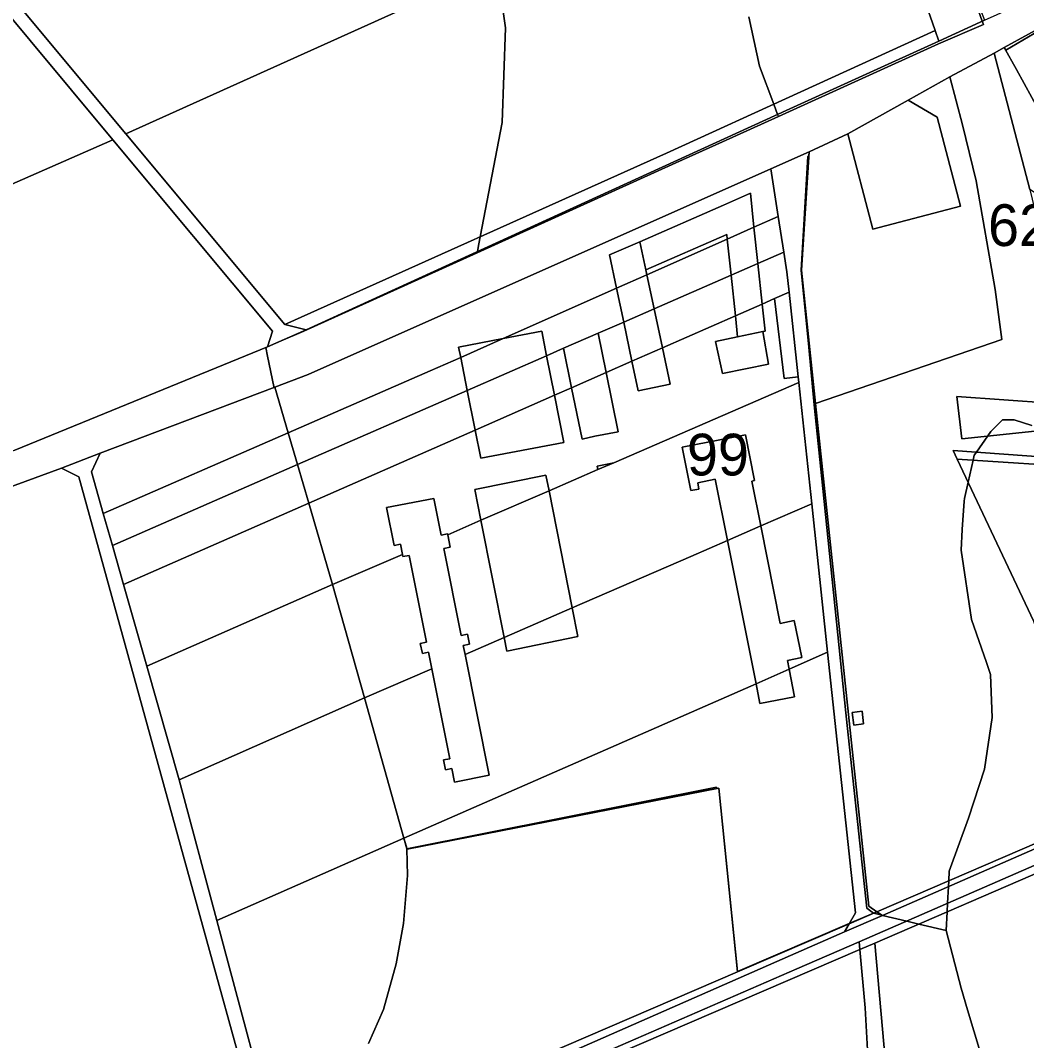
# Model space of a CAD drawing. Extents: x -522079 to -518792, y -1142400 to -1139961.
# Drawn here: x -520985.3 to -520623.1, y -1141173.1 to -1140806 of the extents above; entities that cross this region are included whole.
import ezdxf

# ---------------------------------------------------------------- set-up
doc = ezdxf.new("R2010")
doc.units = 0
for name, color, linetype in [('Bonity', 7, 'Continuous'), ('Hranice parcel', 7, 'Continuous'), ('Parcelní čísla', 7, 'Continuous'), ('Poz předměty', 7, 'Continuous'), ('Značky bodu BP', 7, 'Continuous'), ('Značky budov', 7, 'Continuous'), ('Značky kultur', 7, 'Continuous')]:
    doc.layers.add(name, color=color, linetype=linetype)

msp = doc.modelspace()

# ---------------------------------------------------------------- linework, layer by layer
at = {"layer": 'Bonity'}
for points in [[(-520699.09, -1140943.92), (-520704.17, -1140895.93), (-520701.37, -1140853.35), (-520687.49, -1140846.81), (-520678.48, -1140881.15), (-520646.86, -1140872.86), (-520655.25, -1140840.87), (-520665.74, -1140834.79), (-520650.7, -1140826.31), (-520646.19, -1140843.58), (-520641.23, -1140863.72), (-520634.37, -1140902.81), (-520632.04, -1140920.85)], [(-520879.25, -1141251.61), (-520880.53, -1141246.97), (-520885.33, -1141230.38), (-520883.56, -1141226.59), (-520683.09, -1141140.3), (-520681.18, -1141161.32), (-520680.34, -1141176.38), (-520746.65, -1141201.66), (-520746.38, -1141203.48), (-520757.5, -1141209.45), (-520763.86, -1141219.18), (-520792.12, -1141217.97)]]:
    msp.add_lwpolyline(points, close=True, dxfattribs=at)
at = {"layer": 'Hranice parcel'}
for points in [[(-520657.77, -1140804.5), (-520664.94, -1140785.33), (-520669.15, -1140773.31), (-520674.16, -1140762.17), (-520682.43, -1140743.84), (-520689.02, -1140730.38), (-520701.8, -1140708.2), (-520711.88, -1140691.39), (-520722.11, -1140674.56), (-520715.02, -1140671.04), (-520673.31, -1140722.41), (-520669.12, -1140730.36), (-520666.3, -1140735.71), (-520657.82, -1140755.57), (-520652.69, -1140766.32), (-520641.11, -1140798.37), (-520638.22, -1140805.93), (-520654.73, -1140813.47), (-520656.02, -1140809.72)], [(-520615.7, -1140843.89), (-520626.71, -1140823.74), (-520631.12, -1140815.76), (-520613.67, -1140806.13), (-520609.23, -1140813.72), (-520607.3, -1140817.32), (-520601.28, -1140828.55), (-520598.3, -1140834.1), (-520602.23, -1140836.31)], [(-520654.73, -1140813.47), (-520708.35, -1140837.86), (-520882.47, -1140917.37), (-520890.08, -1140915.49), (-520752.69, -1140853.85), (-520656.02, -1140809.72)], [(-520708.6, -1140903.84), (-520709.39, -1140896.44), (-520710.48, -1140889.38), (-520712.47, -1140876.54), (-520715.12, -1140859.45), (-520701.37, -1140853.35), (-520704.17, -1140895.93), (-520699.09, -1140943.92), (-520679.92, -1141124.76), (-520676.95, -1141126.77), (-520686.99, -1141131.09), (-520684.73, -1141127.15), (-520694.75, -1141033.39), (-520700.46, -1140980.02), (-520705.13, -1140936.35), (-520705.35, -1140934.26)], [(-520893.74, -1140937.98), (-520881.74, -1140933.43), (-520715.12, -1140859.45), (-520712.47, -1140876.54), (-520721.23, -1140880.43), (-520722.52, -1140868.25), (-520732.19, -1140872.47), (-520762.38, -1140885.66), (-520773.2, -1140890.38), (-520770.69, -1140902.38), (-520811.57, -1140920.51), (-520827.55, -1140923.57), (-520826.81, -1140927.27), (-520837.76, -1140932.13), (-520888.93, -1140954.41)], [(-520731.06, -1140883.01), (-520760.22, -1140895.75), (-520762.38, -1140885.66), (-520732.19, -1140872.47), (-520722.52, -1140868.25), (-520721.23, -1140880.43), (-520730.88, -1140884.71)], [(-520712.47, -1140876.54), (-520710.48, -1140889.38), (-520719.85, -1140893.47), (-520721.23, -1140880.43)], [(-520729.49, -1140897.68), (-520730.88, -1140884.71), (-520721.23, -1140880.43), (-520719.85, -1140893.47)], [(-520731.06, -1140883.01), (-520730.88, -1140884.71), (-520759.83, -1140897.56), (-520760.22, -1140895.75)], [(-520730.88, -1140884.71), (-520729.49, -1140897.68), (-520757.2, -1140909.78), (-520759.83, -1140897.56)], [(-520759.83, -1140897.56), (-520770.69, -1140902.38), (-520773.2, -1140890.38), (-520762.38, -1140885.66), (-520760.22, -1140895.75)], [(-520708.6, -1140903.84), (-520713.85, -1140906.14), (-520718.3, -1140908.09), (-520719.85, -1140893.47), (-520710.48, -1140889.38), (-520709.39, -1140896.44)], [(-520718.3, -1140908.09), (-520727.92, -1140912.31), (-520729.49, -1140897.68), (-520719.85, -1140893.47)], [(-520768.14, -1140914.56), (-520770.69, -1140902.38), (-520759.83, -1140897.56), (-520757.2, -1140909.78)], [(-520757.2, -1140909.78), (-520729.49, -1140897.68), (-520727.92, -1140912.31), (-520754.18, -1140923.84)], [(-520789.8, -1140924.02), (-520795.87, -1140926.67), (-520797.62, -1140917.84), (-520811.57, -1140920.51), (-520770.69, -1140902.38), (-520768.14, -1140914.56), (-520777.38, -1140918.59)], [(-520705.35, -1140934.26), (-520710.35, -1140934.87), (-520713.85, -1140906.14), (-520708.6, -1140903.84)], [(-520771.7, -1140965.19), (-520777.69, -1140966.37), (-520777.43, -1140967.67), (-520795, -1140975.29), (-520796.11, -1140969.72), (-520821.72, -1140974.86), (-520819.52, -1140985.91), (-520831.48, -1140991.09), (-520831.54, -1140990.79), (-520833.81, -1140991.24), (-520836.46, -1140978.01), (-520853.53, -1140981.34), (-520850.82, -1140994.93), (-520848.51, -1140994.47), (-520847.77, -1140998.15), (-520872.93, -1141009.05), (-520881.52, -1140979.72), (-520821.62, -1140953.44), (-520819.6, -1140963.59), (-520789.67, -1140957.86), (-520793.04, -1140940.9), (-520786.9, -1140938.2), (-520783.12, -1140956.66), (-520778.49, -1140955.67), (-520770.1, -1140954.09), (-520774.48, -1140932.75), (-520765.19, -1140928.67), (-520762.97, -1140939.31), (-520751.37, -1140936.93), (-520754.18, -1140923.84), (-520727.92, -1140912.31), (-520727.11, -1140919.89), (-520735.04, -1140921.52), (-520732.57, -1140933.11), (-520716.01, -1140929.71), (-520717.99, -1140918.02), (-520717.26, -1140917.87), (-520718.3, -1140908.09), (-520713.85, -1140906.14), (-520710.35, -1140934.87), (-520705.35, -1140934.26), (-520705.13, -1140936.35)], [(-520768.14, -1140914.56), (-520757.2, -1140909.78), (-520754.18, -1140923.84), (-520765.19, -1140928.67)], [(-520718.3, -1140908.09), (-520717.26, -1140917.87), (-520717.99, -1140918.02), (-520727.11, -1140919.89), (-520727.92, -1140912.31)], [(-520765.19, -1140928.67), (-520774.48, -1140932.75), (-520777.38, -1140918.59), (-520768.14, -1140914.56)], [(-520826.81, -1140927.27), (-520811.57, -1140920.51), (-520797.62, -1140917.84), (-520795.87, -1140926.67), (-520824.45, -1140939.15)], [(-520735.04, -1140921.52), (-520727.11, -1140919.89), (-520717.99, -1140918.02), (-520716.01, -1140929.71), (-520732.57, -1140933.11)], [(-520827.55, -1140923.57), (-520811.57, -1140920.51), (-520826.81, -1140927.27)], [(-520777.38, -1140918.59), (-520774.48, -1140932.75), (-520786.9, -1140938.2), (-520789.8, -1140924.02)], [(-520786.9, -1140938.2), (-520793.04, -1140940.9), (-520795.87, -1140926.67), (-520789.8, -1140924.02)], [(-520754.18, -1140923.84), (-520751.37, -1140936.93), (-520762.97, -1140939.31), (-520765.19, -1140928.67)], [(-520837.76, -1140932.13), (-520826.81, -1140927.27), (-520824.45, -1140939.15), (-520885.58, -1140965.84), (-520888.93, -1140954.41)], [(-520793.04, -1140940.9), (-520821.62, -1140953.44), (-520824.45, -1140939.15), (-520795.87, -1140926.67)], [(-520774.48, -1140932.75), (-520770.1, -1140954.09), (-520778.49, -1140955.67), (-520783.12, -1140956.66), (-520786.9, -1140938.2)], [(-520718.75, -1140987.95), (-520721.98, -1140971.84), (-520720.99, -1140971.64), (-520724.28, -1140955.17), (-520747.03, -1140959.63), (-520743.94, -1140975.23), (-520741.04, -1140974.65), (-520741.49, -1140972.39), (-520735.16, -1140971.13), (-520730.77, -1140993.16), (-520743.97, -1140998.9), (-520786.64, -1141017.41), (-520795, -1140975.29), (-520777.43, -1140967.67), (-520771.7, -1140965.19), (-520705.13, -1140936.35), (-520700.46, -1140980.02)], [(-520824.45, -1140939.15), (-520821.62, -1140953.44), (-520881.52, -1140979.72), (-520885.58, -1140965.84)], [(-520789.67, -1140957.86), (-520819.6, -1140963.59), (-520821.62, -1140953.44), (-520793.04, -1140940.9)], [(-520718.75, -1140987.95), (-520730.77, -1140993.16), (-520735.16, -1140971.13), (-520741.49, -1140972.39), (-520741.04, -1140974.65), (-520743.94, -1140975.23), (-520747.03, -1140959.63), (-520724.28, -1140955.17), (-520720.99, -1140971.64), (-520721.98, -1140971.84)], [(-520777.43, -1140967.67), (-520777.69, -1140966.37), (-520771.7, -1140965.19)], [(-520796.11, -1140969.72), (-520795, -1140975.29), (-520819.52, -1140985.91), (-520821.72, -1140974.86)], [(-520811.14, -1141028.03), (-520819.52, -1140985.91), (-520795, -1140975.29), (-520786.64, -1141017.41)], [(-520831.48, -1140991.09), (-520830.61, -1140995.62), (-520832.85, -1140996.06), (-520826.6, -1141027.31), (-520824.37, -1141026.86), (-520823.65, -1141030.49), (-520825.88, -1141030.94), (-520825.24, -1141034.14), (-520816.54, -1141077.66), (-520829.01, -1141080.15), (-520829.99, -1141075.25), (-520832.28, -1141075.7), (-520832.98, -1141072.14), (-520830.7, -1141071.68), (-520837.18, -1141039.32), (-520838.37, -1141033.38), (-520840.62, -1141033.83), (-520841.35, -1141030.21), (-520839.1, -1141029.76), (-520845.35, -1140998.52), (-520847.61, -1140998.97), (-520847.77, -1140998.15), (-520848.51, -1140994.47), (-520850.82, -1140994.93), (-520853.53, -1140981.34), (-520836.46, -1140978.01), (-520833.81, -1140991.24), (-520831.54, -1140990.79)], [(-520704.05, -1141035.32), (-520706.71, -1141021.99), (-520711.86, -1141023.01), (-520718.75, -1140987.95), (-520700.46, -1140980.02), (-520694.75, -1141033.39), (-520708.57, -1141039.45), (-520709.19, -1141036.35)], [(-520811.14, -1141028.03), (-520825.24, -1141034.14), (-520825.88, -1141030.94), (-520823.65, -1141030.49), (-520824.37, -1141026.86), (-520826.6, -1141027.31), (-520832.85, -1140996.06), (-520830.61, -1140995.62), (-520831.48, -1140991.09), (-520819.52, -1140985.91)], [(-520704.05, -1141035.32), (-520709.19, -1141036.35), (-520708.57, -1141039.45), (-520720.5, -1141044.69), (-520730.77, -1140993.16), (-520718.75, -1140987.95), (-520711.86, -1141023.01), (-520706.71, -1141021.99)], [(-520847.24, -1141100.33), (-520861.45, -1141049.84), (-520837.18, -1141039.32), (-520830.7, -1141071.68), (-520832.98, -1141072.14), (-520832.28, -1141075.7), (-520829.99, -1141075.25), (-520829.01, -1141080.15), (-520816.54, -1141077.66), (-520825.24, -1141034.14), (-520811.14, -1141028.03), (-520810.16, -1141032.94), (-520784.59, -1141027.7), (-520786.64, -1141017.41), (-520743.97, -1140998.9), (-520730.77, -1140993.16), (-520720.5, -1141044.69)], [(-520847.61, -1140998.97), (-520845.35, -1140998.52), (-520839.1, -1141029.76), (-520841.35, -1141030.21), (-520840.62, -1141033.83), (-520838.37, -1141033.38), (-520837.18, -1141039.32), (-520861.45, -1141049.84), (-520872.93, -1141009.05), (-520847.77, -1140998.15)], [(-520786.64, -1141017.41), (-520784.59, -1141027.7), (-520810.16, -1141032.94), (-520811.14, -1141028.03)], [(-520727.16, -1141148.38), (-520733.88, -1141082.24), (-520846.14, -1141104.23), (-520847.24, -1141100.33), (-520720.5, -1141044.69), (-520719.07, -1141051.88), (-520706.59, -1141049.39), (-520708.57, -1141039.45), (-520694.75, -1141033.39), (-520684.73, -1141127.15), (-520686.99, -1141131.09)], [(-520706.59, -1141049.39), (-520719.07, -1141051.88), (-520720.5, -1141044.69), (-520708.57, -1141039.45)], [(-520685.9, -1141055.06), (-520682.32, -1141054.61), (-520681.75, -1141059.18), (-520685.33, -1141059.63)], [(-520676.95, -1141126.77), (-520605.48, -1141096), (-520610.52, -1141099.9), (-520675.02, -1141128.07)], [(-520615.64, -1141108.13), (-520612.8, -1141110.04), (-520677.78, -1141138.02), (-520683.09, -1141140.3), (-520683.34, -1141137.56)], [(-520686.99, -1141131.09), (-520676.95, -1141126.77), (-520675.02, -1141128.07), (-520688.68, -1141134.03)], [(-520890.16, -1141218.54), (-520727.16, -1141148.38), (-520686.99, -1141131.09), (-520688.68, -1141134.03), (-520708.05, -1141142.54), (-520885.55, -1141220.5)], [(-520683.34, -1141137.56), (-520683.09, -1141140.3), (-520883.56, -1141226.59), (-520882.39, -1141224.1), (-520705.75, -1141147.3)], [(-520683.09, -1141140.3), (-520677.78, -1141138.02), (-520665.65, -1141273.94), (-520674.18, -1141286.49), (-520680.34, -1141176.38), (-520681.18, -1141161.32)]]:
    msp.add_lwpolyline(points, close=True, dxfattribs=at)
for points in [[(-520987.34, -1140960.66), (-520896.33, -1140923.45), (-520882.47, -1140917.37), (-520708.35, -1140837.86), (-520654.73, -1140813.47), (-520638.22, -1140805.93), (-520618.93, -1140797.21)], [(-520613.67, -1140806.13), (-520631.12, -1140815.76), (-520634.79, -1140817.77), (-520650.7, -1140826.31), (-520665.74, -1140834.79), (-520687.49, -1140846.81), (-520701.37, -1140853.35), (-520715.12, -1140859.45), (-520881.74, -1140933.43), (-520893.74, -1140937.98), (-520956.56, -1140961.79), (-520970.5, -1140967.09), (-521026.59, -1140987.63)], [(-521027.41, -1141281.92), (-520897.83, -1141225.78), (-520885.55, -1141220.5), (-520708.05, -1141142.54), (-520688.68, -1141134.03), (-520675.02, -1141128.07), (-520610.52, -1141099.9), (-520605.48, -1141096), (-520603.47, -1141094.45), (-520599.33, -1141085.41), (-520601.54, -1141117.64), (-520612.8, -1141110.04), (-520615.64, -1141108.13), (-520683.34, -1141137.56), (-520705.75, -1141147.3), (-520882.39, -1141224.1), (-520895.38, -1141229.74), (-521025.25, -1141286.2)]]:
    msp.add_lwpolyline(points, dxfattribs=at)
at = {"layer": 'Parcelní čísla'}
for points in [[(-521187.8, -1140573.75), (-521174.07, -1140567.72), (-521175.11, -1140573.76), (-521134.28, -1140622.71), (-521036.95, -1140739.4), (-520947.33, -1140846.85), (-520890.08, -1140915.49), (-520882.47, -1140917.37), (-520896.33, -1140923.45), (-520894.6, -1140917.89), (-520952.05, -1140848.96), (-521041.47, -1140741.65), (-521139.09, -1140624.65), (-521179.71, -1140575.8)], [(-521036.95, -1140739.4), (-520897.82, -1140676.39), (-520765.71, -1140616.57), (-520757.18, -1140627.06), (-520745.42, -1140642.26), (-520733.42, -1140657.97), (-520724.12, -1140671.61), (-520771, -1140692.05), (-520722.34, -1140745.4), (-520809.38, -1140784.65), (-520947.33, -1140846.85)], [(-520752.69, -1140853.85), (-520890.08, -1140915.49), (-520947.33, -1140846.85), (-520809.38, -1140784.65), (-520722.34, -1140745.4), (-520689.02, -1140730.38), (-520682.43, -1140743.84), (-520674.16, -1140762.17), (-520669.15, -1140773.31), (-520664.94, -1140785.33), (-520657.77, -1140804.5), (-520656.02, -1140809.72)], [(-521234.98, -1140825.42), (-521164.66, -1140794.98), (-521041.47, -1140741.65), (-520952.05, -1140848.96), (-521133.42, -1140928.49), (-521179.82, -1140867.68), (-521217.11, -1140828.01)], [(-521133.42, -1140928.49), (-520952.05, -1140848.96), (-520894.6, -1140917.89), (-520896.33, -1140923.45), (-520987.34, -1140960.66), (-521077.97, -1140999.02), (-521081.12, -1140996.97)], [(-520893.74, -1140937.98), (-520888.93, -1140954.41), (-520955.5, -1140983.4), (-520959.78, -1140968.46), (-520956.56, -1140961.79)], [(-520888.93, -1140954.41), (-520885.58, -1140965.84), (-520952.2, -1140994.93), (-520955.5, -1140983.4)], [(-520948.18, -1141008.97), (-520939.75, -1141038.42), (-520928.14, -1141079.25), (-520914.59, -1141129.89), (-520890.98, -1141218.17), (-520890.16, -1141218.54), (-520895.96, -1141221.04), (-520895.4, -1141219.71), (-520927.66, -1141102.94), (-520964.29, -1140970.32), (-520970.5, -1140967.09), (-520956.56, -1140961.79), (-520959.78, -1140968.46), (-520955.5, -1140983.4), (-520952.2, -1140994.93)], [(-520885.58, -1140965.84), (-520881.52, -1140979.72), (-520948.18, -1141008.97), (-520952.2, -1140994.93)], [(-520895.4, -1141219.71), (-520895.96, -1141221.04), (-521038.45, -1141284.46), (-521072.62, -1141164.33), (-521112.83, -1141022.98), (-521082.18, -1141009.47), (-521026.59, -1140987.63), (-520970.5, -1140967.09), (-520964.29, -1140970.32), (-520927.66, -1141102.94)], [(-520881.52, -1140979.72), (-520872.93, -1141009.05), (-520939.75, -1141038.42), (-520948.18, -1141008.97)], [(-520861.45, -1141049.84), (-520928.14, -1141079.25), (-520939.75, -1141038.42), (-520872.93, -1141009.05)], [(-520847.24, -1141100.33), (-520914.59, -1141129.89), (-520928.14, -1141079.25), (-520861.45, -1141049.84)], [(-520914.59, -1141129.89), (-520847.24, -1141100.33), (-520846.14, -1141104.23), (-520733.88, -1141082.24), (-520727.16, -1141148.38), (-520890.16, -1141218.54), (-520890.98, -1141218.17)]]:
    msp.add_lwpolyline(points, close=True, dxfattribs=at)
at = {"layer": 'Poz předměty'}
for points in [[(-520679.92, -1141124.76), (-520699.09, -1140943.92), (-520632.04, -1140920.85), (-520634.37, -1140902.81), (-520641.23, -1140863.72), (-520646.19, -1140843.58), (-520650.7, -1140826.31), (-520634.79, -1140817.77), (-520621.9, -1140866.86), (-520618.56, -1140880.81), (-520614.37, -1140907.34), (-520612.5, -1140933.48), (-520590.36, -1140946.34), (-520594.75, -1140964.79), (-520649.51, -1140960.76), (-520648.03, -1140963.9), (-520620.51, -1141022.34), (-520612.04, -1141047.58), (-520596.21, -1141046.3), (-520599.33, -1141085.41), (-520603.47, -1141094.45), (-520605.48, -1141096), (-520676.95, -1141126.77)], [(-520614.33, -1140943.77), (-520648.15, -1140941.33), (-520646.42, -1140956.53), (-520615.62, -1140953.33)], [(-520615.62, -1140953.33), (-520646.42, -1140956.53), (-520648.15, -1140941.33), (-520614.33, -1140943.77)], [(-520685.9, -1141055.06), (-520685.33, -1141059.63), (-520681.75, -1141059.18), (-520682.32, -1141054.61)]]:
    msp.add_lwpolyline(points, close=True, dxfattribs=at)
at = {"layer": 'Značky bodu BP'}
for points in [[(-520620.42, -1140810.73), (-520630.61, -1140816.68), (-520631.12, -1140815.76), (-520634.79, -1140817.77), (-520650.7, -1140826.31), (-520665.74, -1140834.79), (-520687.49, -1140846.81), (-520701.37, -1140853.35), (-520701.46, -1140854.77), (-520701.88, -1140854.99), (-520704.24, -1140895.9), (-520701.54, -1140923.59), (-520699.51, -1140944.36), (-520696.42, -1140974.51), (-520688.16, -1141055.16), (-520687.69, -1141059.73), (-520680.61, -1141125.41), (-520678.26, -1141127.27), (-520686.93, -1141130.99), (-520727.17, -1141148.26), (-520733.88, -1141082.24), (-520734.67, -1141082.39), (-520734.72, -1141081.93), (-520846.18, -1141104.09), (-520847.24, -1141100.33), (-520861.45, -1141049.84), (-520872.93, -1141009.05), (-520881.52, -1140979.72), (-520885.58, -1140965.84), (-520888.93, -1140954.41), (-520893.74, -1140937.98), (-520894.04, -1140938.09), (-520894.13, -1140937.77), (-520896.37, -1140926.81), (-520897, -1140923.72), (-520896.33, -1140923.45), (-520892.32, -1140921.69), (-520883.25, -1140917.88), (-520820.87, -1140889.65), (-520749.39, -1140857.3), (-520732.6, -1140849.71), (-520712.43, -1140840.58), (-520654.77, -1140814.48), (-520638.64, -1140807.47), (-520639.05, -1140806.31), (-520652.97, -1140767)], [(-520652.97, -1140767), (-520639.05, -1140806.31), (-520638.64, -1140807.47), (-520654.77, -1140814.48), (-520712.43, -1140840.58), (-520712.59, -1140840.17), (-520712.71, -1140839.85), (-520714.07, -1140836.22), (-520719.2, -1140822.5), (-520723.13, -1140804.75)], [(-520813.84, -1140786.66), (-520810.7, -1140808.74), (-520811.87, -1140842.73), (-520819.78, -1140883.95), (-520820.24, -1140886.37), (-520820.78, -1140889.2), (-520820.87, -1140889.65), (-520883.25, -1140917.88), (-520892.32, -1140921.69), (-520896.33, -1140923.45), (-520897, -1140923.72), (-520896.37, -1140926.81), (-520894.13, -1140937.77), (-520894.04, -1140938.09), (-520893.74, -1140937.98), (-520888.93, -1140954.41), (-520885.58, -1140965.84), (-520881.52, -1140979.72), (-520872.93, -1141009.05), (-520861.45, -1141049.84), (-520847.24, -1141100.33), (-520846.18, -1141104.09), (-520846, -1141113.7), (-520847.36, -1141130.97), (-520850.08, -1141145.51), (-520854.61, -1141161.87), (-520860.04, -1141174.14)], [(-520723.13, -1140804.75), (-520719.2, -1140822.5), (-520714.07, -1140836.22), (-520712.71, -1140839.85), (-520712.59, -1140840.17), (-520712.43, -1140840.58), (-520732.6, -1140849.71), (-520749.39, -1140857.3), (-520820.87, -1140889.65), (-520820.78, -1140889.2), (-520820.24, -1140886.37), (-520819.78, -1140883.95), (-520811.87, -1140842.73), (-520810.7, -1140808.74), (-520813.84, -1140786.66)], [(-520621.19, -1140951.83), (-520627.56, -1140949.7), (-520631.81, -1140949.7), (-520635.53, -1140953.43), (-520635.91, -1140953.96), (-520637.03, -1140955.55), (-520641.12, -1140961.37), (-520641.91, -1140962.49), (-520642.3, -1140964.25), (-520644.1, -1140972.24), (-520645.4, -1140978.03), (-520645.62, -1140979.01), (-520646.24, -1140989.25), (-520646.69, -1140996.59), (-520642.97, -1141021.63), (-520637.57, -1141037.05), (-520636.06, -1141041.35), (-520635.95, -1141044.62), (-520635.53, -1141056.8), (-520638.19, -1141075.44), (-520644.03, -1141093.03), (-520650.94, -1141112.21), (-520651.11, -1141115.64), (-520651.21, -1141117.67), (-520651.51, -1141123.72), (-520651.66, -1141126.77), (-520652, -1141133.52), (-520661.88, -1141131.17), (-520666.25, -1141130.13), (-520674.98, -1141128.05), (-520675.08, -1141128.02), (-520678.17, -1141127.29), (-520678.26, -1141127.27), (-520680.61, -1141125.41), (-520687.69, -1141059.73), (-520688.16, -1141055.16), (-520696.42, -1140974.51), (-520699.51, -1140944.36), (-520701.54, -1140923.59), (-520704.24, -1140895.9), (-520701.88, -1140854.99), (-520701.46, -1140854.77), (-520701.37, -1140853.35), (-520687.49, -1140846.81), (-520665.74, -1140834.79), (-520650.7, -1140826.31), (-520634.79, -1140817.77), (-520631.12, -1140815.76), (-520630.61, -1140816.68), (-520620.42, -1140810.73)], [(-520639.78, -1141177.21), (-520644.35, -1141162.05), (-520646.69, -1141154.3), (-520652, -1141133.52), (-520651.66, -1141126.77), (-520651.51, -1141123.72), (-520651.21, -1141117.67), (-520651.11, -1141115.64), (-520650.94, -1141112.21), (-520644.03, -1141093.03), (-520638.19, -1141075.44), (-520635.53, -1141056.8), (-520635.95, -1141044.62), (-520636.06, -1141041.35), (-520637.57, -1141037.05), (-520642.97, -1141021.63), (-520646.69, -1140996.59), (-520646.24, -1140989.25), (-520645.62, -1140979.01), (-520645.4, -1140978.03), (-520644.1, -1140972.24), (-520642.3, -1140964.25), (-520641.91, -1140962.49), (-520641.12, -1140961.37), (-520637.03, -1140955.55), (-520635.91, -1140953.96), (-520635.53, -1140953.43), (-520631.81, -1140949.7), (-520627.56, -1140949.7), (-520621.19, -1140951.83)], [(-520860.04, -1141174.14), (-520854.61, -1141161.87), (-520850.08, -1141145.51), (-520847.36, -1141130.97), (-520846, -1141113.7), (-520846.18, -1141104.09), (-520734.72, -1141081.93), (-520734.67, -1141082.39), (-520733.88, -1141082.24), (-520727.17, -1141148.26), (-520686.93, -1141130.99), (-520678.26, -1141127.27), (-520678.17, -1141127.29), (-520675.08, -1141128.02), (-520674.98, -1141128.05), (-520666.25, -1141130.13), (-520661.88, -1141131.17), (-520652, -1141133.52), (-520646.69, -1141154.3), (-520644.35, -1141162.05), (-520639.78, -1141177.21)]]:
    msp.add_lwpolyline(points, dxfattribs=at)
at = {"layer": 'Značky budov'}
msp.add_lwpolyline([(-520607.02, -1141187.64), (-520665.65, -1141273.94), (-520677.78, -1141138.02), (-520612.8, -1141110.04), (-520601.54, -1141117.64), (-520606.07, -1141183.78)], close=True, dxfattribs=at)
at = {"layer": 'Značky kultur'}
for points in [[(-520607.5, -1140876.29), (-520621.9, -1140866.86), (-520634.79, -1140817.77), (-520631.12, -1140815.76), (-520626.71, -1140823.74), (-520615.7, -1140843.89), (-520602.23, -1140836.31)], [(-520655.25, -1140840.87), (-520646.86, -1140872.86), (-520678.48, -1140881.15), (-520687.49, -1140846.81), (-520665.74, -1140834.79)], [(-520649.51, -1140960.76), (-520594.75, -1140964.79), (-520599.73, -1140986.18), (-520599.81, -1140983.06), (-520599.94, -1140978.24), (-520600.24, -1140966.98), (-520648.03, -1140963.9)], [(-520620.51, -1141022.34), (-520648.03, -1140963.9), (-520600.24, -1140966.98), (-520604.67, -1140967.12), (-520604.41, -1140978.31), (-520604.3, -1140983.07), (-520599.81, -1140983.06), (-520599.73, -1140986.18), (-520599.09, -1141003), (-520600.97, -1141003.07), (-520601.06, -1141001.34), (-520601.36, -1141001.34), (-520602.52, -1141000.7), (-520603.99, -1141000.76), (-520605.04, -1141001.54), (-520605.37, -1141001.56), (-520605.29, -1141003.25), (-520607.09, -1141003.32), (-520615.08, -1141003.61), (-520614.42, -1141021.92), (-520598.37, -1141020.83), (-520596.21, -1141046.3), (-520612.04, -1141047.58)]]:
    msp.add_lwpolyline(points, close=True, dxfattribs=at)

# ---------------------------------------------------------------- texts
at = {"layer": 'Značky bodu BP'}
for s, rotation, p in [('62411/III.', 360, (-520636.98, -1140887.21)), ('99', 0, (-520745.36, -1140969.76))]:
    msp.add_text(s, height=15, rotation=rotation, dxfattribs=at).set_placement(p)

doc.saveas('drawing.dxf')
